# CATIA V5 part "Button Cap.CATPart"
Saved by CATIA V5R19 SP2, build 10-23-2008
Part number: Button Cap
Definition: Button Cap
Nomenclature: Button Cap
Source: Unknown
Bounding box of the stored display mesh (mm): x -14.875 to 14.875, y -14.875 to 14.875, z -21.2 to -6.2
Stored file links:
  Z:\fausse table rondelle-20220905T211342Z-001\fausse table rondelle\Button Cap.CATPart
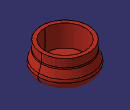
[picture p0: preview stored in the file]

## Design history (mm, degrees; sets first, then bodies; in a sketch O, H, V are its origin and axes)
AxisSystem1: origin (0, 0, 0), X (1, 0, 0), Y (0, 1, 0), Z (0, 0, 1)
Body1 "Button Cap" (main body)
  Solid1: solid without history
Body2 "Arrow 1"
  Solid2: solid without history
Body3 "Arrow 2"
  Solid3: solid without history
Body4 "Arrow 3"
  Solid4: solid without history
